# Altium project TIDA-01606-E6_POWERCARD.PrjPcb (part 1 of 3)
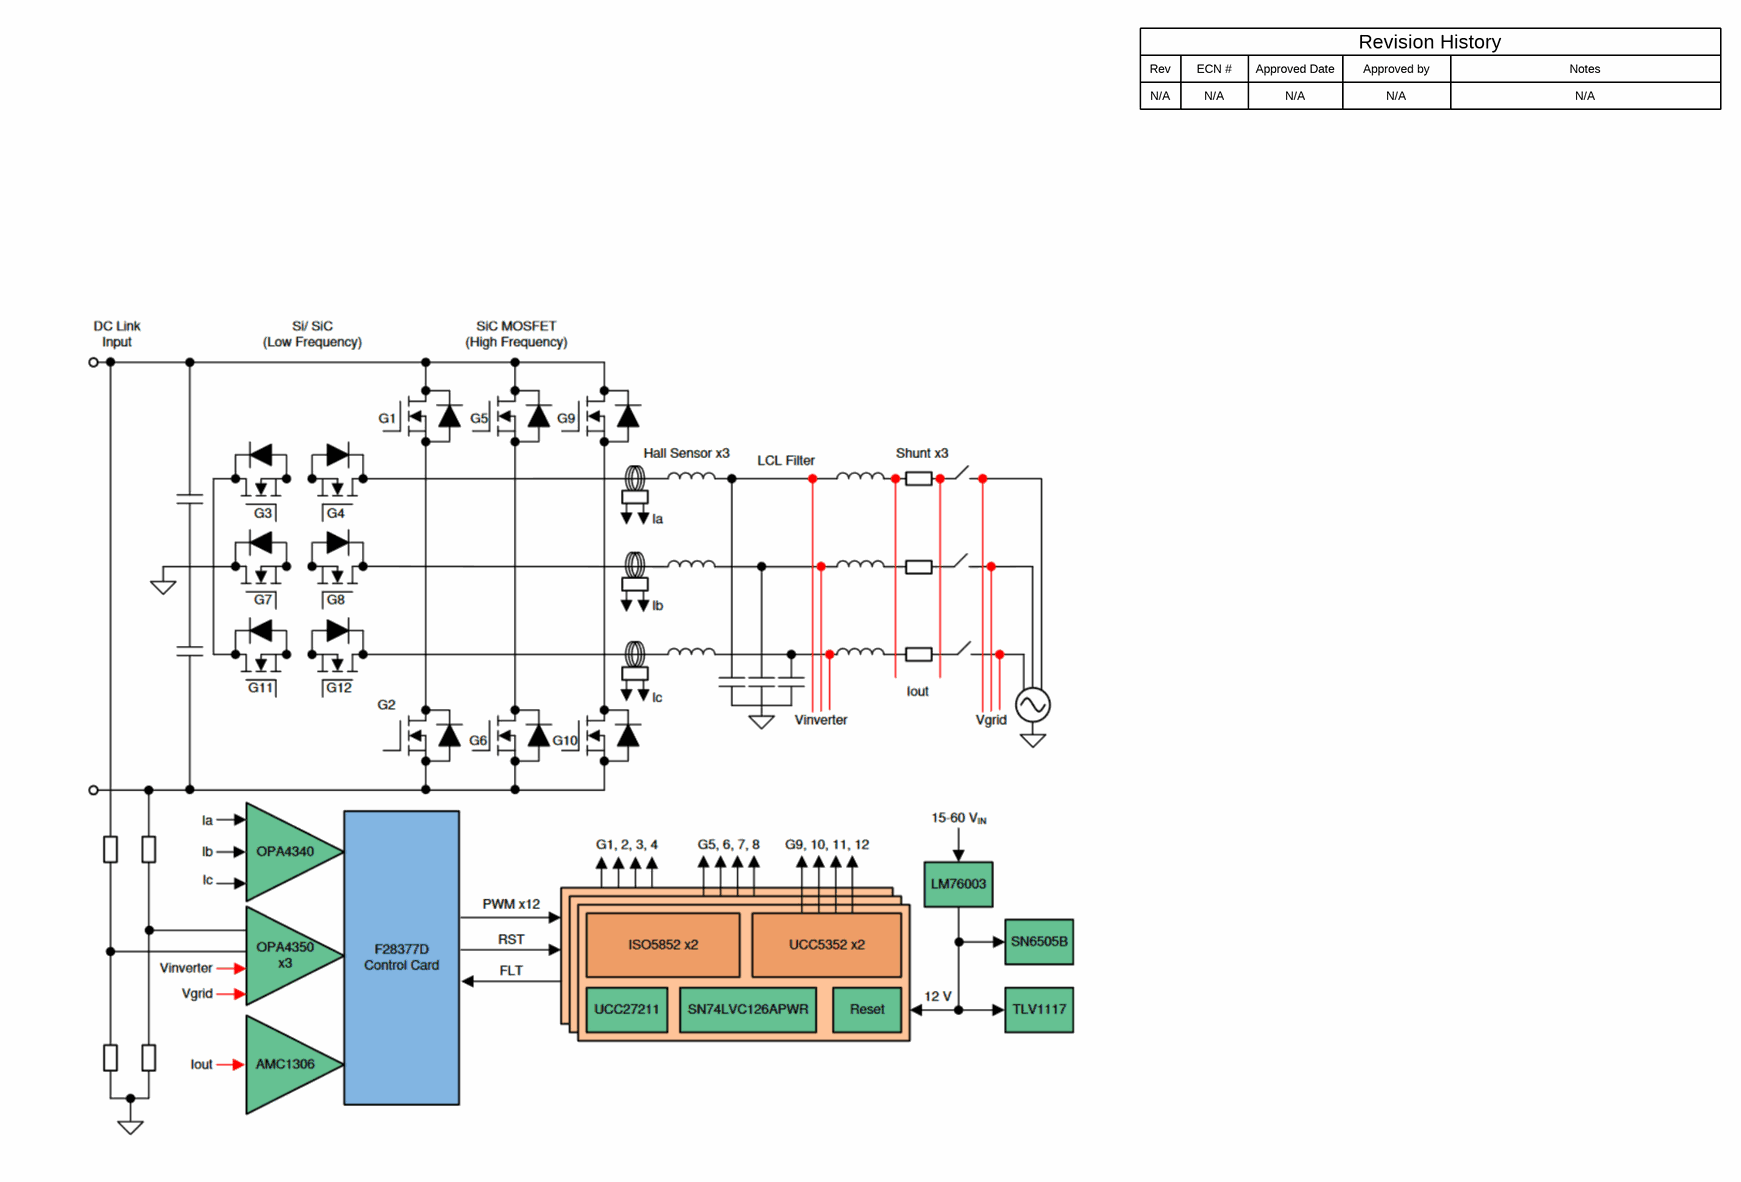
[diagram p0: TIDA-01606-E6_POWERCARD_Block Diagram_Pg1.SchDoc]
CopyrightYear: 2018; EVM_Orderable: NA; PCB_Layout: Bart Basile; PCB_Rev: E5; PRJ_Customer: Public Release; PRJ_Engineer: Bart Basile; PRJ_Number: TIDA-01606_Power Card; PRJ_Title: 10KW Inverter; SCH_Rev: E5; TechSupport: http://www.ti.com/support; TID: TIDA-01606
7 sheets, 551 parts. Net scope: global (net labels, ports and power ports of the same name join across sheets).
Board file: TIDA-01606-E6_POWERCARD.PcbDoc
Sheets:
  TIDA-01606-E6_POWERCARD_Block Diagram_Pg1.SchDoc
  TIDA-01606-E6_POWERCARD_Controller Card_Pg6.SchDoc
  TIDA-01606-E6_POWERCARD_Current Sensing_Pg5.SchDoc
  TIDA-01606-E6_POWERCARD_Hardware_Pg7.SchDoc
  TIDA-01606-E6_POWERCARD_Power Stage_Pg2.SchDoc
  TIDA-01606-E6_POWERCARD_Power Supply and Protection_Pg3.SchDoc
  TIDA-01606-E6_POWERCARD_Voltage Sensing_Pg4.SchDoc

## Sheet TIDA-01606-E6_POWERCARD_Block Diagram_Pg1.SchDoc
size 431 x 279 mm; Date: Not shown in title block; ApprovedBy: Not shown in title block; CheckedBy: Not shown in title block; Author: Not shown in title block; CompanyName: Not shown in title block; DrawnBy: Murali P; Engineer: Not shown in title block; Organization: Not shown in title block; Address1: Not shown in title block; Address2: Not shown in title block; Address3: Not shown in title block; Address4: Not shown in title block; DocumentNumber: 1; Revision: Use project parameter SCH_Rev; SheetNumber: 1; SheetTotal: 7; PageSetup: Record=PageOptions¦CenterHorizontal=True¦CenterVertical=True¦PrintScale=1.00¦XCorrection=1.00¦YCorrection=1.00¦PrintKind=0¦BorderSize=5000000¦LeftOffset=0¦BottomOffset=0¦Orientation=2¦PaperLength=1000¦PaperWidth=1000¦Scale=100¦PaperSource=15¦PrintQuality=600¦MediaType=1¦DitherType=10¦PaperKind=Letter¦PrintScaleMode=1

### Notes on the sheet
- Rev
- N/A
- ECN #
- Approved Date
- Approved by
- Revision History
- Notes

## Sheet TIDA-01606-E6_POWERCARD_Controller Card_Pg6.SchDoc
size 431 x 279 mm; Date: Not shown in title block; ApprovedBy: Not shown in title block; CheckedBy: Not shown in title block; Author: Not shown in title block; CompanyName: Not shown in title block; DrawnBy: Murali P; Engineer: Not shown in title block; Organization: Not shown in title block; Address1: Not shown in title block; Address2: Not shown in title block; Address3: Not shown in title block; Address4: Not shown in title block; DocumentNumber: 1; Revision: Use project parameter SCH_Rev; SheetNumber: 6; SheetTotal: 7; PageSetup: Record=PageOptions¦CenterHorizontal=True¦CenterVertical=True¦PrintScale=1.00¦XCorrection=1.00¦YCorrection=1.00¦PrintKind=0¦BorderSize=5000000¦LeftOffset=0¦BottomOffset=0¦Orientation=2¦PaperLength=1000¦PaperWidth=1000¦Scale=100¦PaperSource=15¦PrintQuality=600¦MediaType=1¦DitherType=10¦PrintScaleMode=1¦PaperKind=Letter
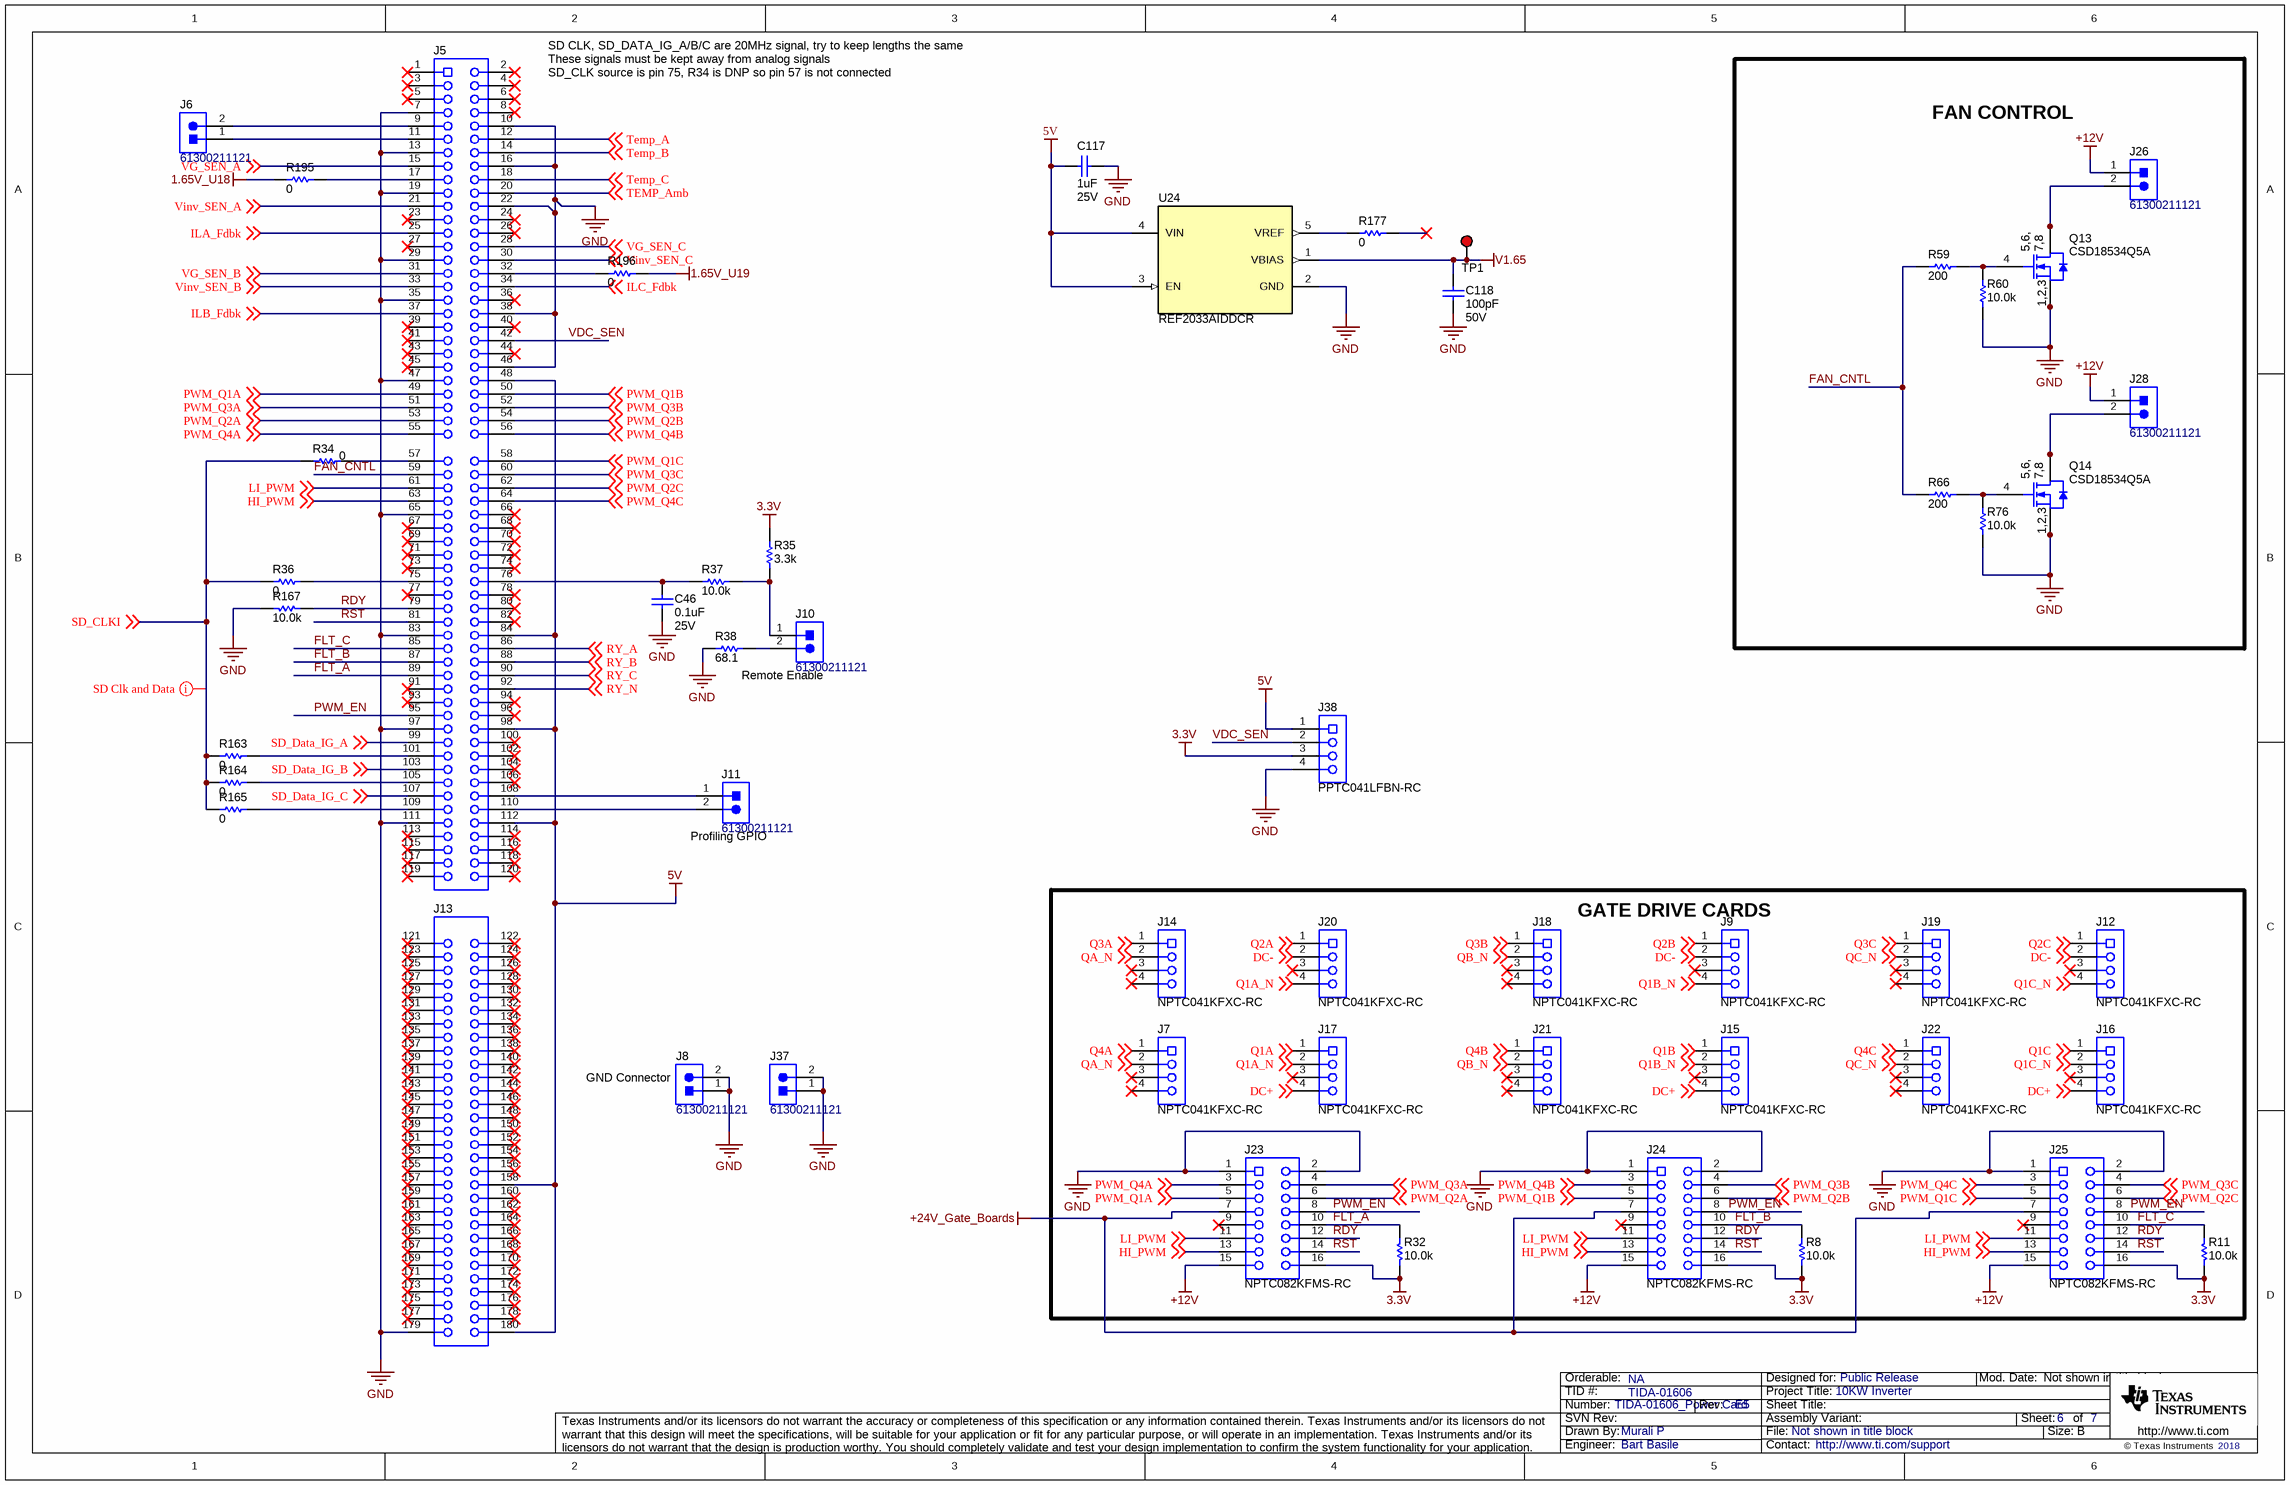
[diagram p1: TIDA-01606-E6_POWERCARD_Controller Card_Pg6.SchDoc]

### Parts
C46  ValueDisplayed: 0.1uF  VDC_V: 25V  [0603]  (hidden comment: C0603X104K3RACTU)
C117  ValueDisplayed: 1uF  VDC_V: 25V  [0603]  (hidden comment: C0603C105K3RACTU)
C118  ValueDisplayed: 100pF  VDC_V: 50V  [0603]  (hidden comment: CL10B101KB8NNNC)
J5  HSEC8-160-01-L-DV-A-BL  [controlCARD-120HSEC]  (value not drawn)
J6  61300211121  [WURTH_61300211121]
J7  NPTC041KFXC-RC  [Sullins_xPxC041KFXC-RC]
J8  61300211121  [WURTH_61300211121]
J9  NPTC041KFXC-RC  [Sullins_xPxC041KFXC-RC]
J10  61300211121  [WURTH_61300211121]
J11  61300211121  [WURTH_61300211121]
J12  NPTC041KFXC-RC  [Sullins_xPxC041KFXC-RC]
J13  HSEC8-130-01-L-DV-A  [controlCARD-180HSEC-60pinAddon]  (value not drawn)
J14  NPTC041KFXC-RC  [Sullins_xPxC041KFXC-RC]
J15  NPTC041KFXC-RC  [Sullins_xPxC041KFXC-RC]
J16  NPTC041KFXC-RC  [Sullins_xPxC041KFXC-RC]
J17  NPTC041KFXC-RC  [Sullins_xPxC041KFXC-RC]
J18  NPTC041KFXC-RC  [Sullins_xPxC041KFXC-RC]
J19  NPTC041KFXC-RC  [Sullins_xPxC041KFXC-RC]
J20  NPTC041KFXC-RC  [Sullins_xPxC041KFXC-RC]
J21  NPTC041KFXC-RC  [Sullins_xPxC041KFXC-RC]
J22  NPTC041KFXC-RC  [Sullins_xPxC041KFXC-RC]
J23  NPTC082KFMS-RC  [Sullins_xPxC082KFMS-RC]
J24  NPTC082KFMS-RC  [Sullins_xPxC082KFMS-RC]
J25  NPTC082KFMS-RC  [Sullins_xPxC082KFMS-RC]
J26  61300211121  [WURTH_61300211121]
J28  61300211121  [WURTH_61300211121]
J37  61300211121  [WURTH_61300211121]
J38  PPTC041LFBN-RC  [Sullins_xPxC041LFBN]
Q13  CSD18534Q5A  [DQJ0008A]
Q14  CSD18534Q5A  [DQJ0008A]
R8  ValueDisplayed: 10.0k  [0603]  (hidden comment: ERJ-3EKF1002V)
R11  ValueDisplayed: 10.0k  [0603]  (hidden comment: ERJ-3EKF1002V)
R32  ValueDisplayed: 10.0k  [0603]  (hidden comment: ERJ-3EKF1002V)
R34  ValueDisplayed: 0  [0603]  (hidden comment: RCS06030000Z0EA)
R35  ValueDisplayed: 3.3k  [0805_HV]  (hidden comment: CRCW08053K30JNEA)
R36  ValueDisplayed: 0  [0603]  (hidden comment: RCS06030000Z0EA)
R37  ValueDisplayed: 10.0k  [0603]  (hidden comment: ERJ-3EKF1002V)
R38  ValueDisplayed: 68.1  [0603]  (hidden comment: CRCW060368R1FKEA)
R59  ValueDisplayed: 200  [0805_HV]  (hidden comment: CRCW0805200RFKEA)
R60  ValueDisplayed: 10.0k  [0603]  (hidden comment: ERJ-3EKF1002V)
R66  ValueDisplayed: 200  [0805_HV]  (hidden comment: CRCW0805200RFKEA)
R76  ValueDisplayed: 10.0k  [0603]  (hidden comment: ERJ-3EKF1002V)
R163  ValueDisplayed: 0  [0603]  (hidden comment: RCS06030000Z0EA)
R164  ValueDisplayed: 0  [0603]  (hidden comment: RCS06030000Z0EA)
R165  ValueDisplayed: 0  [0603]  (hidden comment: RCS06030000Z0EA)
R167  ValueDisplayed: 10.0k  [0603]  (hidden comment: ERJ-3EKF1002V)
R177  ValueDisplayed: 0  [0805_HV]  (hidden comment: ERJ-6GEY0R00V)
R195  ValueDisplayed: 0  [0805_HV]  (hidden comment: ERJ-6GEY0R00V)
R196  ValueDisplayed: 0  [0805_HV]  (hidden comment: ERJ-6GEY0R00V)
TP1  5000  [Keystone5000]  (value not drawn)
U24  REF2033AIDDCR  [DDC0005A_N]

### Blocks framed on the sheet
FAN CONTROL: J26 J28 Q13 Q14 R59 R60 R66 R76
GATE DRIVE CARDS: J7 J9 J12 J14-J25 R8 R11 R32

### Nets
1.65V_U18: R195.2
1.65V_U19: R196.2
3.3V: J23.16 J24.16 J25.16 J38.3 R8.2 R11.2 R32.2 R35.2
5V: C117.2 J5.48 J5.84 J5.98 J5.112 J13.158 J13.180 J38.1 U24.3(EN) U24.4(VIN)
+12V: J23.15 J24.15 J25.15 J26.1 J28.1
+24V_Gate_Boards: J23.7 J24.7 J25.7
GND: C46.1 C117.1 C118.2 J5.7 J5.10 J5.13 J5.16 J5.19 J5.22 J5.29 J5.35 J5.38 J5.46 J5.47 J5.65 J5.83 J5.97 J5.111 J8.1 J8.2 J13.179 J23.1 J23.2 J24.1 J24.2 J25.1 J25.2 J37.1 J37.2 J38.4 Q13.1(S) Q13.2(S) Q13.3(S) Q14.1(S) Q14.2(S) Q14.3(S) R38.1 R60.1 R76.1 R167.1 U24.2(GND)
V1.65: C118.1 TP1.1 U24.1(VBIAS)
DC+: J15.4 J16.4 J17.4 ; off-sheet DC+
DC-: J9.2 J12.2 J20.2 ; off-sheet DC-
FAN_CNTL: J5.59 R59.1 R66.1
FLT_A: J5.89 J23.10 R32.1
FLT_B: J5.87 J24.10 R8.1
FLT_C: J5.85 J25.10 R11.1
HI_PWM: J5.63 J23.13 J24.13 J25.13 ; off-sheet HI_PWM
ILA_Fdbk: J5.25 ; off-sheet ILA_Fdbk
ILB_Fdbk: J5.37 ; off-sheet ILB_Fdbk
ILC_Fdbk: J5.34 ; off-sheet ILC_Fdbk
LI_PWM: J5.61 J23.11 J24.11 J25.11 ; off-sheet LI_PWM
PWM_EN: J5.95 J23.8 J24.8 J25.8
PWM_Q1A: J5.49 J23.5 ; off-sheet PWM_Q1A
PWM_Q1B: J5.50 J24.5 ; off-sheet PWM_Q1B
PWM_Q1C: J5.58 J25.5 ; off-sheet PWM_Q1C
PWM_Q2A: J5.53 J23.6 ; off-sheet PWM_Q2A
PWM_Q2B: J5.54 J24.6 ; off-sheet PWM_Q2B
PWM_Q2C: J5.62 J25.6 ; off-sheet PWM_Q2C
PWM_Q3A: J5.51 J23.4 ; off-sheet PWM_Q3A
PWM_Q3B: J5.52 J24.4 ; off-sheet PWM_Q3B
PWM_Q3C: J5.60 J25.4 ; off-sheet PWM_Q3C
PWM_Q4A: J5.55 J23.3 ; off-sheet PWM_Q4A
PWM_Q4B: J5.56 J24.3 ; off-sheet PWM_Q4B
PWM_Q4C: J5.64 J25.3 ; off-sheet PWM_Q4C
Q1A: J17.1 ; off-sheet Q1A
Q1A_N: J17.2 J20.4 ; off-sheet Q1A_N  [project net Iind_A]
Q1B: J15.1 ; off-sheet Q1B
Q1B_N: J9.4 J15.2 ; off-sheet Q1B_N  [project net Iind_B]
Q1C: J16.1 ; off-sheet Q1C
Q1C_N: J12.4 J16.2 ; off-sheet Q1C_N  [project net Iind_C]
Q2A: J20.1 ; off-sheet Q2A
Q2B: J9.1 ; off-sheet Q2B
Q2C: J12.1 ; off-sheet Q2C
Q3A: J14.1 ; off-sheet Q3A
Q3B: J18.1 ; off-sheet Q3B
Q3C: J19.1 ; off-sheet Q3C
Q4A: J7.1 ; off-sheet Q4A
Q4B: J21.1 ; off-sheet Q4B
Q4C: J22.1 ; off-sheet Q4C
QA_N: J7.2 J14.2 ; off-sheet QA_N
QB_N: J18.2 J21.2 ; off-sheet QB_N
QC_N: J19.2 J22.2 ; off-sheet QC_N
RDY: J5.79 J23.12 J24.12 J25.12 R167.2
RST: J5.81 J23.14 J24.14 J25.14
RY_A: J5.86 ; off-sheet RY_A
RY_B: J5.88 ; off-sheet RY_B
RY_C: J5.90 ; off-sheet RY_C
RY_N: J5.92 ; off-sheet RY_N
SD_CLKI: R34.1 R36.1 R163.1 R164.1 R165.1 ; off-sheet SD_CLKI
SD_Data_IG_A: J5.99 ; off-sheet SD_Data_IG_A
SD_Data_IG_B: J5.103 ; off-sheet SD_Data_IG_B
SD_Data_IG_C: J5.107 ; off-sheet SD_Data_IG_C
Temp_A: J5.12 ; off-sheet Temp_A
TEMP_Amb: J5.20 ; off-sheet TEMP_Amb
Temp_B: J5.14 ; off-sheet Temp_B
Temp_C: J5.18 ; off-sheet Temp_C
VDC_SEN: J5.42 J38.2
VG_SEN_A: J5.15 ; off-sheet VG_SEN_A
VG_SEN_B: J5.31 ; off-sheet VG_SEN_B
VG_SEN_C: J5.28 ; off-sheet VG_SEN_C
Vinv_SEN_A: J5.21 ; off-sheet Vinv_SEN_A
Vinv_SEN_B: J5.33 ; off-sheet Vinv_SEN_B
Vinv_SEN_C: J5.30 ; off-sheet Vinv_SEN_C
NetC46_2: C46.2 J5.76 R37.2
NetJ5_9: J5.9 J6.2
NetJ5_11: J5.11 J6.1
NetJ5_17: J5.17 R195.1
NetJ5_32: J5.32 R196.1
NetJ5_57: J5.57 R34.2
NetJ5_75: J5.75 R36.2
NetJ5_101: J5.101 R163.2
NetJ5_105: J5.105 R164.2
NetJ5_108: J5.108 J11.1
NetJ5_109: J5.109 R165.2
NetJ5_110: J5.110 J11.2
NetJ10_1: J10.1 R35.1 R37.1
NetJ10_2: J10.2 R38.2
NetJ26_2: J26.2 Q13.5(D) Q13.6(D) Q13.7(D) Q13.8(D) Q13.9(D)
NetJ28_2: J28.2 Q14.5(D) Q14.6(D) Q14.7(D) Q14.8(D) Q14.9(D)
NetQ13_4: Q13.4(G) R59.2 R60.2
NetQ14_4: Q14.4(G) R66.2 R76.2
NetR177_2: R177.2 U24.5(VREF)

Not connected (* = marked no-connect by the designer): J5 1* 2* 3* 4* 5* 6* 8* 23* 24* 26* 27* 36* 39* 40* 41* 43* 44* 45* 66* 67* 68* 69* 70* 71* 72* 73* 74* 77* 78* 80* 82* 91* 93* 94* 96* 100* 102* 104* 106* 113* 114* 115* 116* 117* 118* 119* 120*; J7 3* 4*; J9 3*; J12 3*; J13 121* 122* 123* 124* 125* 126* 127* 128* 129* 130* 131* 132* 133* 134* 135* 136* 137* 138* 139* 140* 141* 142* 143* 144* 145* 146* 147* 148* 149* 150* 151* 152* 153* 154* 155* 156* 157* 159* 160* 161* 162* 163* 164* 165* 166* 167* 168* 169* 170* 171* 172* 173* 174* 175* 176* 177* 178*; J14 3* 4*; J15 3*; J16 3*; J17 3*; J18 3* 4*; J19 3* 4*; J20 3*; J21 3* 4*; J22 3* 4*; J23 9*; J24 9*; J25 9*; R177 1*

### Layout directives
rule Undefined: SD_CLKI

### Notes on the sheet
- (near J5) These signals must be kept away from analog signals
- (near J5) SD_CLK source is pin 75, R34 is DNP so pin 57 is not connected
- SD CLK, SD_DATA_IG_A/B/C are 20MHz signal, try to keep lengths the same
- Remote Enable
- (near J11) Profiling GPIO
- (near J8) GND Connector

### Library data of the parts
C46 = CMP-0006979-5: CAP, CERM, 0.1 uF, 25 V, +/- 10%, X7R, 0603; Manufacturer: Kemet; Polarized: N; Value: 0.1uF; U/M: EA; Cap_F: 100nF; Value1: Unknown; TaMin_C: -55°C; TaMax_C: 125°C; AEC Category: Q200; SizeArea_mm2: 1.28; SizeAreaWB_mm2: 4.68; SizeX_mm: 1.6; SizeY_mm: 0.8; SizeZ_mm: 1
C117 = CMP-0006867-4: CAP, CERM, 1 uF, 25 V, +/- 10%, X7R, 0603; Manufacturer: Kemet; Polarized: N; Value: 1uF; U/M: EA; Cap_F: 1µF; Value1: Unknown; TaMin_C: -55°C; TaMax_C: 125°C; AEC Category: Q200; SizeArea_mm2: 1.28; SizeAreaWB_mm2: 4.68; SizeX_mm: 1.6; SizeY_mm: 0.8; SizeZ_mm: 1
C118 = CMP-0083857-1: CAP, CERM, 100 pF, 50 V,+/- 10%, X7R, 0603; Manufacturer: Samsung Electro-Mechanics; Polarized: N; Value: 100pF; U/M: EA; TaMin_C: -55°C; TaMax_C: 125°C; SizeArea_mm2: 1.28; SizeAreaWB_mm2: 4.68; SizeX_mm: 1.6; SizeY_mm: 0.8; SizeZ_mm: 1; AEC Category: Q200
J5 = CMP-0003814-2: C2000 controlCARD-120HSEC connector, SMT; Manufacturer: Samtec; Note: The pin numbering does not match Samtec datasheet
J6 J8 J10 J11 J26 J28 J37 = CMP-0054794-2: Header, 2.54 mm, 2x1, Gold, TH; Manufacturer: Wurth Elektronik; Green_Lifecycle: Active; Green_REACh: Passed; Cert_UL: Y; Gender: Male; Pitch_mm: 2.54; Row_Count: 1; Shrouded: N
J7 J9 J12 J14-J22 = CMP-0083775-2: Receptacle, 2.54mm, 4x1, Tin, SMT; Manufacturer: Sullins Connector Solutions; Pitch_mm: 2.54; Gender: Female; Voltage_V: 250V; CompType: Socket Strip; Row_Count: 1; Current_A: 3A; Cert_UL: Y
J13 = CMP-0003859-2: C2000 controlCARD-180HSEC (60-pin addon) connector, SMT; Manufacturer: Samtec; Note: The pin numbering does not match Samtec datasheet
J23-J25 = CMP-0083774-2: Receptacle, 2.54mm, 8x2, Tin, SMT; Manufacturer: Sullins Connector Solutions; Current_A: 3A; Gender: Female; Voltage_V: 250V; CompType: Socket Strip; Row_Count: 2; RowSpacing_mm: 2.54; Cert_UL: Y
J38 = CMP-0054676-1: Receptacle, 2.54mm, 4x1, Tin, TH; Manufacturer: Sullins Connector Solutions; CompType: Socket Strip; Pitch_mm: 2.54; Gender: Female; Row_Count: 1; Current_A: 3A; Voltage_V: 250V; Cert_UL: Y; CNHeader: FALSE; CT: TRUE
Q13 Q14 = CMP-0000817-1: MOSFET, N-CH, 60 V, 50 A, DQJ0008A (VSONP-8); Manufacturer: Texas Instruments; Alternate Manufacturer: None; U/M: EA; ChType: N; Value: 60V; Value1: 0.009; Rdson45_ohm: 9.8m; Value2: 22 nC; QgTyp_nC: 22; Vgs_V: 2.3V; IdsMax_A: 50A; SizeAreaWB_mm2: 55.2; SizeArea_mm2: 29.4; SizeX_mm: 6; SizeY_mm: 4.9; SizeZ_mm: 1.1; AEC Category: Q101
R8 R11 R32 R60 R76 R167 = CMP-0022684-3: RES, 10.0 k, 1%, 0.1 W, 0603; Manufacturer: Panasonic; Value: 10.0k; Res_ohm: 10k; Value_Code: 10k0; Power_W: 100mW; Value2: 0.1W; VDC_V: 75V; TempCo: 100 ppm/C; SizeArea_mm2: 1.28; SizeX_mm: 1.6; SizeY_mm: 0.8; SizeZ_mm: 1; EIA_Code: E96; U/M: EA; AEC Category: Q200
R34 R36 R163-R165 = CMP-0081973-1: RES, 0, 0%, 0.25 W, AEC-Q200 Grade 0, 0603; Manufacturer: Vishay-Dale; SizeAreaWB_mm2: 4.68; SizeArea_mm2: 1.28; AEC Qualified: Y; AEC Category: Q200; Value: 0; SizeZ_mm: 1; SizeY_mm: 0.8; Power_W: 250mW; Value2: 0.25W; SizeX_mm: 1.6
R35 = CMP-0020539-3: RES, 3.3 k, 5%, 0.125 W, AEC-Q200 Grade 0, 0805; Manufacturer: Vishay-Dale; Value: 3.3k; Value_Code: 3k30; Power_W: 125mW; Value2: 0.125W; VDC_V: 150V; TempCo: 200 ppm/C; EIA_Code: E24; AEC Category: Q200; AEC Qualified: Y; AEC Grade: 0; SizeArea_mm2: 2.5; SizeX_mm: 2; SizeY_mm: 1.25; SizeZ_mm: 1.45
R37 = CMP-0022684-3: RES, 10.0 k, 1%, 0.1 W, 0603; Manufacturer: Panasonic; Value: 10.0k; Res_ohm: 10k; Value_Code: 10k0; Power_W: 100mW; Value2: 0.1W; VDC_V: 75V; TempCo: 100 ppm/C; EIA_Code: E96; U/M: EA; AEC Category: Q200; SizeArea_mm2: 1.28; SizeX_mm: 1.6; SizeY_mm: 0.8; SizeZ_mm: 1
R38 = CMP-0022553-4: RES, 68.1, 1%, 0.1 W, AEC-Q200 Grade 0, 0603; Manufacturer: Vishay-Dale; Value: 68.1; Value_Code: 68R1; Power_W: 100mW; Value2: 0.1W; VDC_V: 75V; TempCo: 100 ppm/C; SizeArea_mm2: 1.28; SizeX_mm: 1.6; SizeY_mm: 0.8; SizeZ_mm: 1; EIA_Code: E96; AEC Category: Q200; AEC Qualified: Y; AEC Grade: 0
R59 R66 = CMP-0021039-3: RES, 200, 1%, 0.125 W, AEC-Q200 Grade 0, 0805; Manufacturer: Vishay-Dale; Value: 200; Value_Code: 200R; Power_W: 125mW; Value2: 0.125W; VDC_V: 150V; TempCo: 100 ppm/C; SizeArea_mm2: 2.5; SizeX_mm: 2; SizeY_mm: 1.25; SizeZ_mm: 1.45; EIA_Code: E96; AEC Category: Q200; AEC Qualified: Y; AEC Grade: 0
R177 R195 R196 = CMP-0020616-3: RES, 0, 5%, 0.125 W, AEC-Q200 Grade 0, 0805; Manufacturer: Panasonic; Value: 0; Value_Code: 0000; Power_W: 125mW; Value2: 0.125W; VDC_V: 150V; TempCo: 600 ppm/C; EIA_Code: E24; AEC Category: Q200; AEC Qualified: Y; SizeArea_mm2: 2.5; SizeX_mm: 2; SizeY_mm: 1.25; SizeZ_mm: 1.45; SizeAreaWB_mm2: 6.75
TP1 = CMP-0055137-1: Test Point, Miniature, Red, TH; Manufacturer: Keystone; CNHeader: FALSE; ContactFinish: Silver; CT: TRUE; Green_Lifecycle: Active; Green_REACh: Passed
U24 = CMP-0066190-1: Low-Drift, Low-Power, Dual-Output VREF and VREF/2 Voltage Reference, DDC0005A (SOT-23-T-5); Alternate PartNumber: REF2033AIDDCT; Manufacturer: Texas Instruments; CompType: IC; U/M: EA; SizeArea_mm2: 8.12; SizeAreaWB_mm2: 14.82; SizeX_mm: 2.8; SizeY_mm: 2.9; SizeZ_mm: 1.1

## Sheet TIDA-01606-E6_POWERCARD_Current Sensing_Pg5.SchDoc: Inductor Current Sensing Interface Circuit
size 431 x 279 mm; Date: Not shown in title block; ApprovedBy: Not shown in title block; CheckedBy: Not shown in title block; Author: Not shown in title block; CompanyName: Not shown in title block; DrawnBy: Murali P; Engineer: Not shown in title block; Organization: Not shown in title block; Address1: Not shown in title block; Address2: Not shown in title block; Address3: Not shown in title block; Address4: Not shown in title block; DocumentNumber: 1; Revision: Use project parameter SCH_Rev; SheetNumber: 3; SheetTotal: 7; PageSetup: Record=PageOptions¦CenterHorizontal=True¦CenterVertical=True¦PrintScale=1.00¦XCorrection=1.00¦YCorrection=1.00¦PrintKind=0¦BorderSize=5000000¦LeftOffset=0¦BottomOffset=0¦Orientation=2¦PaperLength=1000¦PaperWidth=1000¦Scale=100¦PaperSource=15¦PrintQuality=600¦MediaType=1¦DitherType=10¦PaperKind=Letter¦PrintScaleMode=1
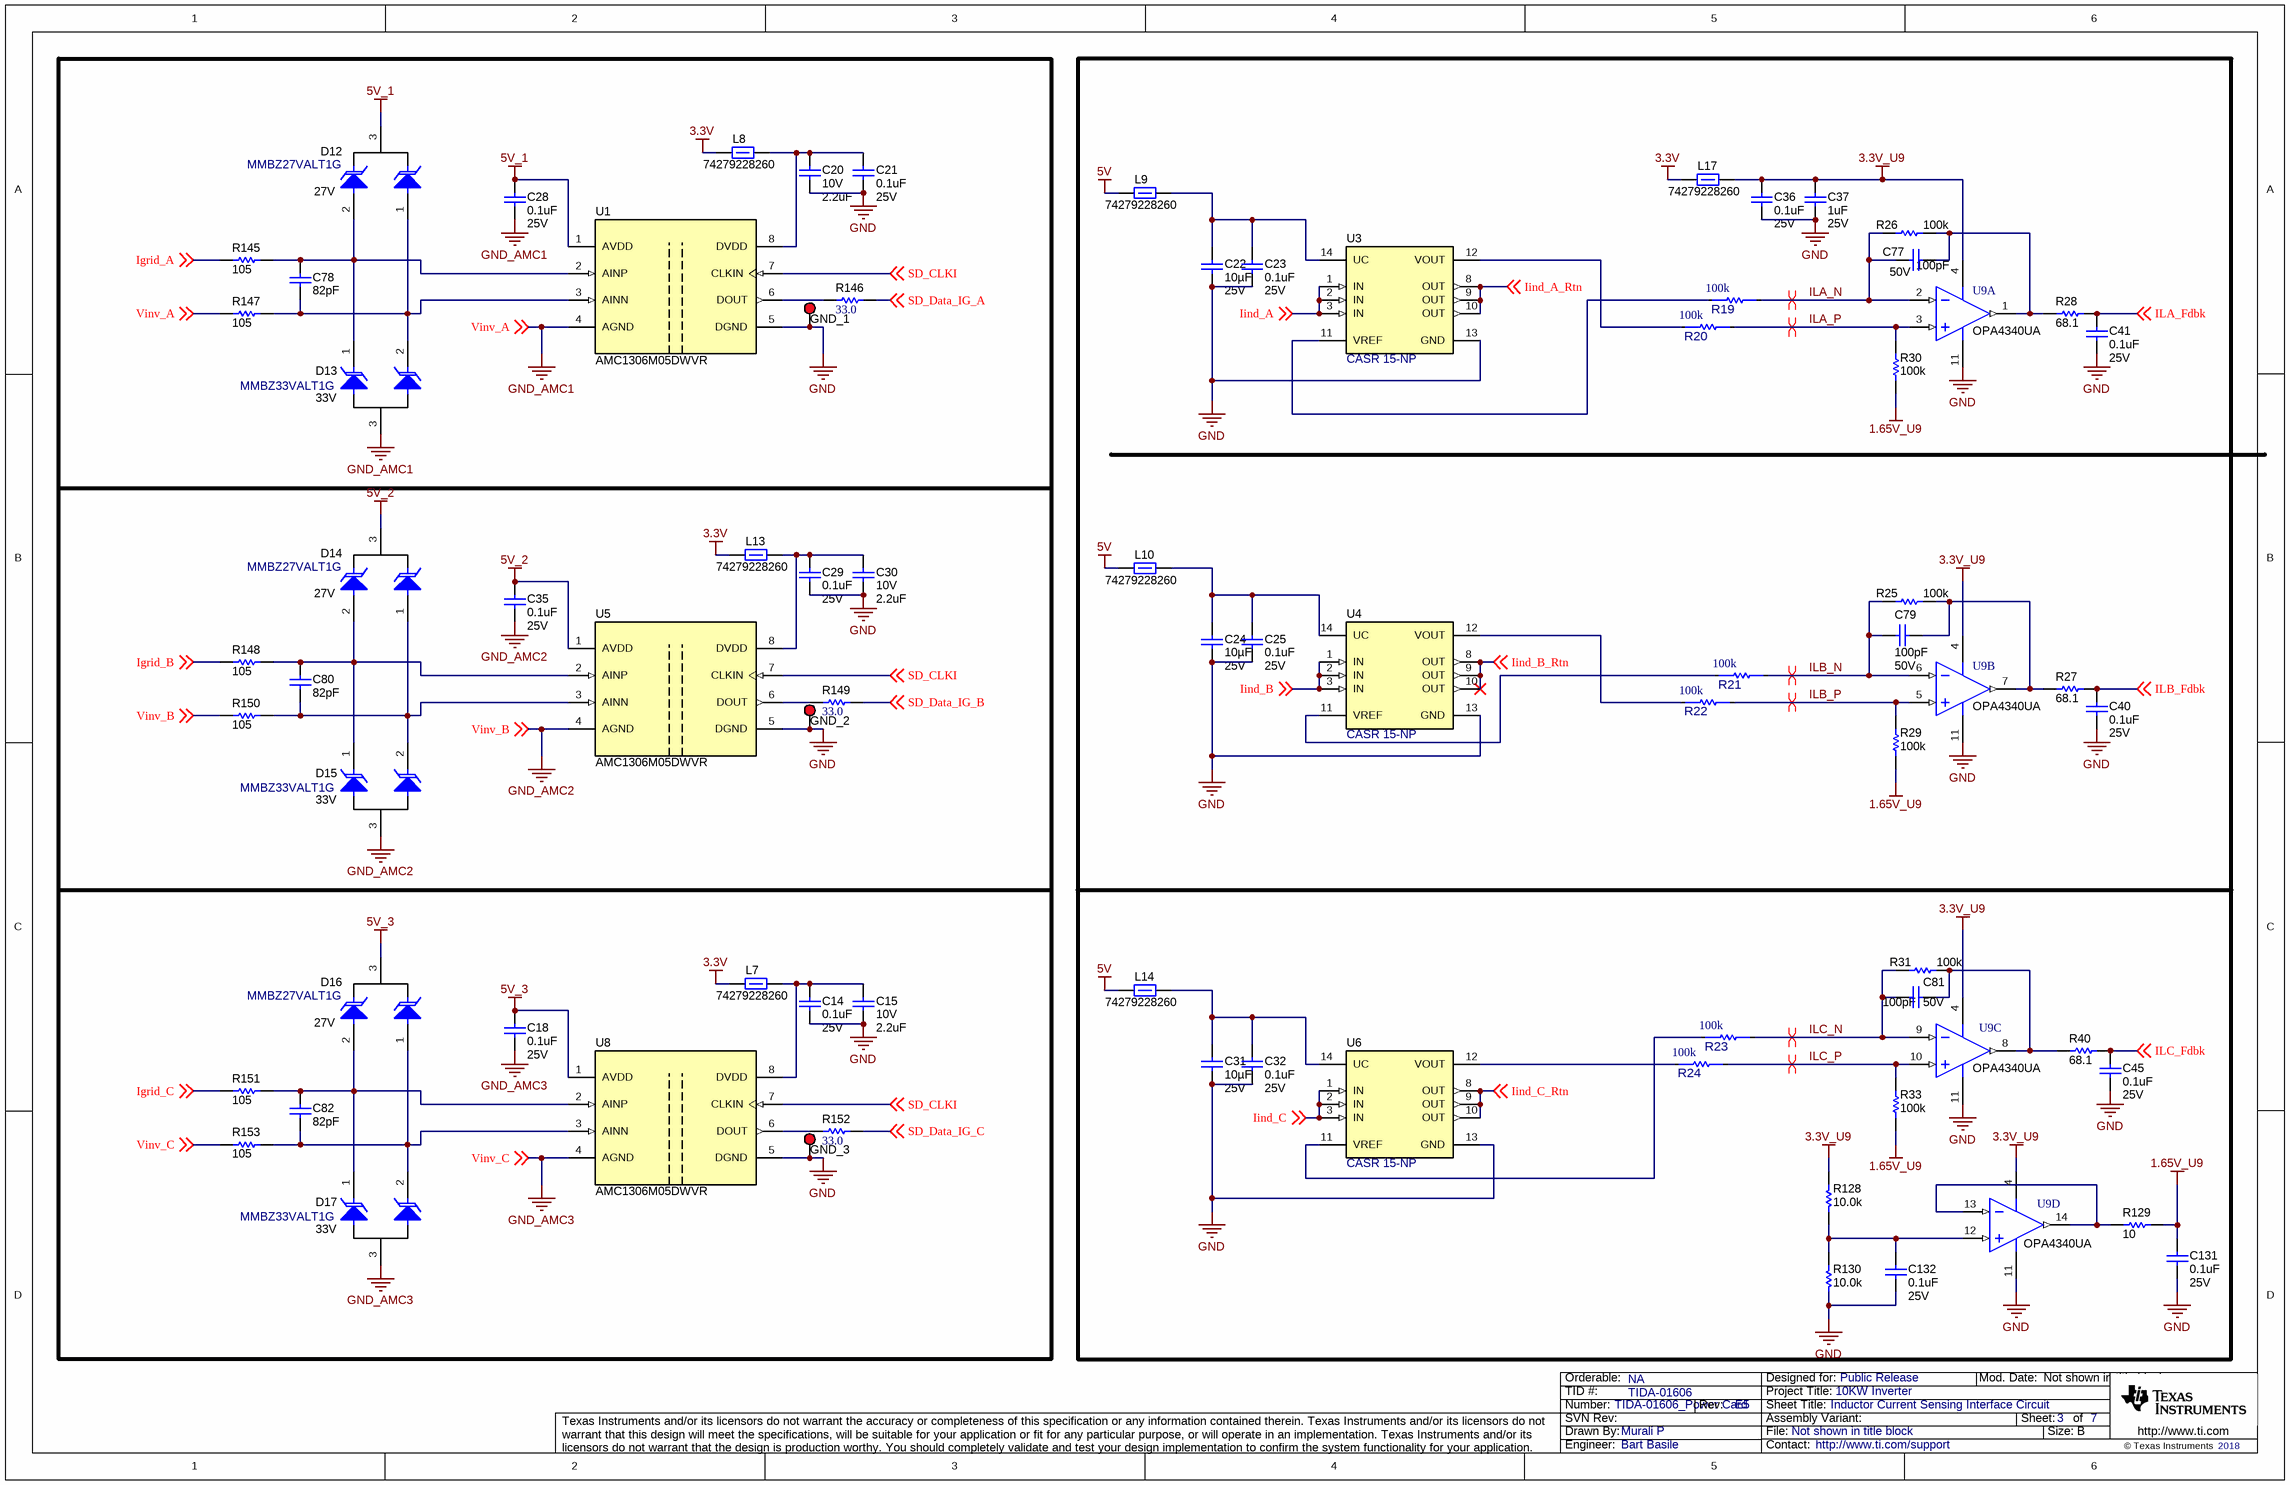
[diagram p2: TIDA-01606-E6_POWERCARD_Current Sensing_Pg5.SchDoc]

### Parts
C14  ValueDisplayed: 0.1uF  VDC_V: 25V  [0603]  (hidden comment: C0603X104K3RACTU)
C15  VDC_V: 10V  ValueDisplayed: 2.2uF  [0805_HV]  (hidden comment: GRM216R61A225KE24D)
C18  ValueDisplayed: 0.1uF  VDC_V: 25V  [0603]  (hidden comment: C0603X104K3RACTU)
C20  VDC_V: 10V  ValueDisplayed: 2.2uF  [0805_HV]  (hidden comment: GRM216R61A225KE24D)
C21  ValueDisplayed: 0.1uF  VDC_V: 25V  [0603]  (hidden comment: C0603X104K3RACTU)
C22  ValueDisplayed: 10µF  VDC_V: 25V  [1206_180]  (hidden comment: C3216X7R1E106K160AB)
C23  ValueDisplayed: 0.1uF  VDC_V: 25V  [0603]  (hidden comment: C0603X104K3RACTU)
C24  ValueDisplayed: 10µF  VDC_V: 25V  [1206_180]  (hidden comment: C3216X7R1E106K160AB)
C25  ValueDisplayed: 0.1uF  VDC_V: 25V  [0603]  (hidden comment: C0603X104K3RACTU)
C28  ValueDisplayed: 0.1uF  VDC_V: 25V  [0603]  (hidden comment: C0603X104K3RACTU)
C29  ValueDisplayed: 0.1uF  VDC_V: 25V  [0603]  (hidden comment: C0603X104K3RACTU)
C30  VDC_V: 10V  ValueDisplayed: 2.2uF  [0805_HV]  (hidden comment: GRM216R61A225KE24D)
C31  ValueDisplayed: 10µF  VDC_V: 25V  [1206_180]  (hidden comment: C3216X7R1E106K160AB)
C32  ValueDisplayed: 0.1uF  VDC_V: 25V  [0603]  (hidden comment: C0603X104K3RACTU)
C35  ValueDisplayed: 0.1uF  VDC_V: 25V  [0603]  (hidden comment: C0603X104K3RACTU)
C36  ValueDisplayed: 0.1uF  VDC_V: 25V  [0603]  (hidden comment: C0603X104K3RACTU)
C37  ValueDisplayed: 1uF  VDC_V: 25V  [0603]  (hidden comment: C0603C105K3RACTU)
C40  ValueDisplayed: 0.1uF  VDC_V: 25V  [0603]  (hidden comment: C0603X104K3RACTU)
C41  ValueDisplayed: 0.1uF  VDC_V: 25V  [0603]  (hidden comment: C0603X104K3RACTU)
C45  ValueDisplayed: 0.1uF  VDC_V: 25V  [0603]  (hidden comment: C0603X104K3RACTU)
C77  ValueDisplayed: 100pF  VDC_V: 50V  [0603]  (hidden comment: CL10B101KB8NNNC)
C78  ValueDisplayed: 82pF  [0603]  (hidden comment: 06035A820JAT2A)
C79  ValueDisplayed: 100pF  VDC_V: 50V  [0603]  (hidden comment: CL10B101KB8NNNC)
C80  ValueDisplayed: 82pF  [0603]  (hidden comment: 06035A820JAT2A)
C81  ValueDisplayed: 100pF  VDC_V: 50V  [0603]  (hidden comment: CL10B101KB8NNNC)
C82  ValueDisplayed: 82pF  [0603]  (hidden comment: 06035A820JAT2A)
C131  ValueDisplayed: 0.1uF  VDC_V: 25V  [0603]  (hidden comment: C0603X104K3RACTU)
C132  ValueDisplayed: 0.1uF  VDC_V: 25V  [0603]  (hidden comment: C0603X104K3RACTU)
D12  MMBZ27VALT1G  value 27V  [SOT-23]
D13  MMBZ33VALT1G  value 33V  [SOT-23]
D14  MMBZ27VALT1G  value 27V  [SOT-23]
D15  MMBZ33VALT1G  value 33V  [SOT-23]
D16  MMBZ27VALT1G  value 27V  [SOT-23]
D17  MMBZ33VALT1G  value 33V  [SOT-23]
GND_1  5000  [Keystone5000]  (value not drawn)
GND_2  5000  [Keystone5000]  (value not drawn)
GND_3  5000  [Keystone5000]  (value not drawn)
L7  74279228260  [0603]
L8  74279228260  [0603]
L9  74279228260  [0603]
L10  74279228260  [0603]
L13  74279228260  [0603]
L14  74279228260  [0603]
L17  74279228260  [0603]
R19  value 100k  [FP-ERJ-PB3B1003V_0603-MFG]  (hidden comment: ERJ-PB3B1003V)
R20  value 100k  [FP-ERJ-PB3B1003V_0603-MFG]  (hidden comment: ERJ-PB3B1003V)
R21  value 100k  [FP-ERJ-PB3B1003V_0603-MFG]  (hidden comment: ERJ-PB3B1003V)
R22  value 100k  [FP-ERJ-PB3B1003V_0603-MFG]  (hidden comment: ERJ-PB3B1003V)
R23  value 100k  [FP-ERJ-PB3B1003V_0603-MFG]  (hidden comment: ERJ-PB3B1003V)
R24  value 100k  [FP-ERJ-PB3B1003V_0603-MFG]  (hidden comment: ERJ-PB3B1003V)
R25  ValueDisplayed: 100k  [0603]  (hidden comment: CRCW0603100KFKEA)
R26  ValueDisplayed: 100k  [0603]  (hidden comment: CRCW0603100KFKEA)
R27  ValueDisplayed: 68.1  [0603]  (hidden comment: CRCW060368R1FKEA)
R28  ValueDisplayed: 68.1  [0603]  (hidden comment: CRCW060368R1FKEA)
R29  ValueDisplayed: 100k  [0603]  (hidden comment: CRCW0603100KFKEA)
R30  ValueDisplayed: 100k  [0603]  (hidden comment: CRCW0603100KFKEA)
R31  ValueDisplayed: 100k  [0603]  (hidden comment: CRCW0603100KFKEA)
R33  ValueDisplayed: 100k  [0603]  (hidden comment: CRCW0603100KFKEA)
R40  ValueDisplayed: 68.1  [0603]  (hidden comment: CRCW060368R1FKEA)
R128  ValueDisplayed: 10.0k  [0603]  (hidden comment: RG1608P-103-B-T5)
R129  ValueDisplayed: 10  [0603]  (hidden comment: CRCW060310R0JNEA)
R130  ValueDisplayed: 10.0k  [0603]  (hidden comment: RG1608P-103-B-T5)
R145  ValueDisplayed: 105  [0603]  (hidden comment: CRCW0603105RFKEA)
R146  ValueDisplayed: 33.0  [0603]  (hidden comment: RC0603FR-0733RL)
R147  ValueDisplayed: 105  [0603]  (hidden comment: CRCW0603105RFKEA)
R148  ValueDisplayed: 105  [0603]  (hidden comment: CRCW0603105RFKEA)
R149  ValueDisplayed: 33.0  [0603]  (hidden comment: RC0603FR-0733RL)
R150  ValueDisplayed: 105  [0603]  (hidden comment: CRCW0603105RFKEA)
R151  ValueDisplayed: 105  [0603]  (hidden comment: CRCW0603105RFKEA)
R152  ValueDisplayed: 33.0  [0603]  (hidden comment: RC0603FR-0733RL)
R153  ValueDisplayed: 105  [0603]  (hidden comment: CRCW0603105RFKEA)
U1  AMC1306M05DWVR  [DWV0008A]
U3  CASR 15-NP  [CASR]
U4  CASR 15-NP  [CASR]
U5  AMC1306M05DWVR  [DWV0008A]
U6  CASR 15-NP  [CASR]
U8  AMC1306M05DWVR  [DWV0008A]
U9  OPA4340UA  [D0014A_N]  (parts A,B,C,D of 4)

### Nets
1.65V_U9: C131.2 R29.1 R30.1 R33.1 R129.2
3.3V: L7.1 L8.1 L13.1 L17.1
3.3V_U9: C36.2 C37.1 L17.2 R128.1 U9.4(V+)
5V: L9.1 L10.1 L14.1
5V_1: C28.1 D12.3 U1.1(AVDD)
5V_2: C35.1 D14.3 U5.1(AVDD)
5V_3: C18.1 D16.3 U8.1(AVDD)
GND: C14.1 C15.2 C20.2 C21.1 C22.2 C23.2 C24.2 C25.2 C29.1 C30.2 C31.2 C32.2 C36.1 C37.2 C40.1 C41.1 C45.1 C131.1 C132.1 GND_1.1 GND_2.1 GND_3.1 R130.2 U1.5(DGND) U3.13(GND) U4.13(GND) U5.5(DGND) U6.13(GND) U8.5(DGND) U9.11(V-)
GND_AMC1: C28.2 D13.3(A) R147.1 U1.4(AGND) ; off-sheet Vinv_A  [also labelled Vinv_A]
GND_AMC2: C35.2 D15.3(A) R150.1 U5.4(AGND) ; off-sheet Vinv_B  [also labelled Vinv_B]
GND_AMC3: C18.2 D17.3(A) R153.1 U8.4(AGND) ; off-sheet Vinv_C  [also labelled Vinv_C]
Igrid_A: R145.1 ; off-sheet Igrid_A
Igrid_B: R148.1 ; off-sheet Igrid_B
Igrid_C: R151.1 ; off-sheet Igrid_C
Iind_A: U3.1(IN) U3.2(IN) U3.3(IN) ; off-sheet Iind_A
Iind_A_Rtn: U3.8(OUT) U3.9(OUT) U3.10(OUT) ; off-sheet Iind_A_Rtn
Iind_B: U4.1(IN) U4.2(IN) U4.3(IN) ; off-sheet Iind_B
Iind_B_Rtn: U4.8(OUT) U4.9(OUT) U4.10(OUT) ; off-sheet Iind_B_Rtn
Iind_C: U6.1(IN) U6.2(IN) U6.3(IN) ; off-sheet Iind_C
Iind_C_Rtn: U6.8(OUT) U6.9(OUT) U6.10(OUT) ; off-sheet Iind_C_Rtn
ILA_Fdbk: C41.2 R28.2 ; off-sheet ILA_Fdbk
ILA_N: C77.2 R19.2 R26.1 U9.2(IN_A-)
ILA_P: R20.2 R30.2 U9.3(IN_A+)
ILB_Fdbk: C40.2 R27.2 ; off-sheet ILB_Fdbk
ILB_N: C79.2 R21.2 R25.1 U9.6(IN_B-)
ILB_P: R22.2 R29.2 U9.5(IN_B+)
ILC_Fdbk: C45.2 R40.2 ; off-sheet ILC_Fdbk
ILC_N: C81.2 R23.2 R31.1 U9.9(IN_C-)
ILC_P: R24.2 R33.2 U9.10(IN_C+)
SD_CLKI: U1.7(CLKIN) U5.7(CLKIN) U8.7(CLKIN) ; off-sheet SD_CLKI
SD_Data_IG_A: R146.2 ; off-sheet SD_Data_IG_A
SD_Data_IG_B: R149.2 ; off-sheet SD_Data_IG_B
SD_Data_IG_C: R152.2 ; off-sheet SD_Data_IG_C
NetC14_2: C14.2 C15.1 L7.2 U8.8(DVDD)
NetC20_1: C20.1 C21.2 L8.2 U1.8(DVDD)
NetC22_1: C22.1 C23.1 L9.2 U3.14(UC)
NetC24_1: C24.1 C25.1 L10.2 U4.14(UC)
NetC29_2: C29.2 C30.1 L13.2 U5.8(DVDD)
NetC31_1: C31.1 C32.1 L14.2 U6.14(UC)
NetC77_1: C77.1 R26.2 R28.1 U9.1(OUT_A)
NetC78_1: C78.1 D12.2 D13.1(C) R145.2 U1.2(AINP)
NetC78_2: C78.2 D12.1 D13.2(C) R147.2 U1.3(AINN)
NetC79_1: C79.1 R25.2 R27.1 U9.7(OUT_B)
NetC80_1: C80.1 D14.2 D15.1(C) R148.2 U5.2(AINP)
NetC80_2: C80.2 D14.1 D15.2(C) R150.2 U5.3(AINN)
NetC81_1: C81.1 R31.2 R40.1 U9.8(OUT_C)
NetC82_1: C82.1 D16.2 D17.1(C) R151.2 U8.2(AINP)
NetC82_2: C82.2 D16.1 D17.2(C) R153.2 U8.3(AINN)
NetC132_2: C132.2 R128.2 R130.1 U9.12(IN_D+)
NetR19_1: R19.1 U3.11(VREF)
NetR20_1: R20.1 U3.12(VOUT)
NetR21_1: R21.1 U4.11(VREF)
NetR22_1: R22.1 U4.12(VOUT)
NetR23_1: R23.1 U6.11(VREF)
NetR24_1: R24.1 U6.12(VOUT)
NetR129_1: R129.1 U9.13(IN_D-) U9.14(OUT_D)
NetR146_1: R146.1 U1.6(DOUT)
NetR149_1: R149.1 U5.6(DOUT)
NetR152_1: R152.1 U8.6(DOUT)

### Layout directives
differential pair: ILA_N, ILA_P, ILB_N, ILB_P, ILC_N, ILC_P

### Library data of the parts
C14 C18 C21 C23 C25 C28 C29 C32 C35 = CMP-0006979-5: as C46 on sheet TIDA-01606-E6_POWERCARD_Controller Card_Pg6
C15 C20 C30 = CMP-0008132-2: CAP, CERM, 2.2 uF, 10 V, +/- 10%, X5R, 0805; Manufacturer: MuRata; TaMin_C: -55°C; Polarized: N; SizeAreaWB_mm2: 6.75; Value1: 0.009 ohm; U/M: EA; Value: 2.2uF; TaMax_C: 85°C; SizeZ_mm: 1.45; SizeX_mm: 2; SizeY_mm: 1.25; Cap_Case: 0805; SizeArea_mm2: 2.5; Cap_F: 2.2µF; AEC Category: Q200; ESR_ohm: 9m
C22 C24 C31 = CMP-0080740-1: CAP, CERM, 10 µF, 25 V,+/- 10%, X7R, 1206; Manufacturer: TDK; Polarized: N; Value: 10uF; U/M: EA; TaMin_C: -55°C; TaMax_C: 125°C; Cap_Case: 1206; AEC Category: Q200; SizeArea_mm2: 5.12; SizeAreaWB_mm2: 10.92; SizeX_mm: 3.2; SizeY_mm: 1.6; SizeZ_mm: 1.8
C36 C40 C41 C45 C131 C132 = CMP-0006979-5: CAP, CERM, 0.1 uF, 25 V, +/- 10%, X7R, 0603; Manufacturer: Kemet; Polarized: N; Value: 0.1uF; U/M: EA; Cap_F: 100nF; Value1: Unknown; TaMin_C: -55°C; TaMax_C: 125°C; SizeArea_mm2: 1.28; SizeAreaWB_mm2: 4.68; SizeX_mm: 1.6; SizeY_mm: 0.8; SizeZ_mm: 1; AEC Category: Q200
C37 = CMP-0006867-4: CAP, CERM, 1 uF, 25 V, +/- 10%, X7R, 0603; Manufacturer: Kemet; Polarized: N; Value: 1uF; U/M: EA; Cap_F: 1µF; Value1: Unknown; TaMin_C: -55°C; TaMax_C: 125°C; SizeArea_mm2: 1.28; SizeAreaWB_mm2: 4.68; SizeX_mm: 1.6; SizeY_mm: 0.8; SizeZ_mm: 1; AEC Category: Q200
C77 C79 C81 = CMP-0083857-1: as C118 on sheet TIDA-01606-E6_POWERCARD_Controller Card_Pg6
C78 C80 C82 = CMP-0006799-4: CAP, CERM, 82 pF, 50 V, +/- 5%, C0G/NP0, 0603; Manufacturer: AVX; Polarized: N; Value: 82pF; U/M: EA; ESR_ohm: 1.31d; Value1: 0.131 ohm; VDC_V: 50V; TaMin_C: -55°C; TaMax_C: 125°C; SizeArea_mm2: 1.28; SizeAreaWB_mm2: 4.68; SizeX_mm: 1.6; SizeY_mm: 0.8; SizeZ_mm: 1; AEC Category: Q200
D12 D14 D16 = CMP-0005922-4: Diode, TVS, Uni, 27 V, SOT-23; Manufacturer: ON Semiconductor; Value1: 40W; RJA_CperW: 556; SizeAreaWB_mm2: 14; SizeArea_mm2: 7.5; SizeX_mm: 2.5; SizeY_mm: 3; SizeZ_mm: 1.1; AEC Category: Q101
D13 D15 D17 = CMP-0005926-4: Diode, TVS, Uni, 33 V, 46 Vc, SOT-23; Manufacturer: ON Semiconductor; Value1: 40W; RJA_CperW: 417; SizeAreaWB_mm2: 14; SizeArea_mm2: 7.5; SizeX_mm: 2.5; SizeY_mm: 3; SizeZ_mm: 1.1; AEC Category: Q101; AEC Qualified: N; Ipp: 870mA; Vbr_Max: 34.65V; Vbr_Min: 31.35V; Vc: 46V
GND_1-GND_3 = CMP-0055137-1: as TP1 on sheet TIDA-01606-E6_POWERCARD_Controller Card_Pg6
L7-L10 L13 L14 L17 = CMP-0003155-2: Ferrite Bead, 26 ohm @ 100 MHz, 6.5 A, 0603; Manufacturer: Wurth Elektronik; Ztyp@1GHz_Ohm: 35.506; ZTyp@100MHz_Ohm: 26; SizeAreaWB_mm2: 4.68; DCR_ohm: 5m; Value1: 0.005 ohm; Value: 26 ohm; Imax_A: 6.5A; SizeZ_mm: 1; SizeX_mm: 1.6; SizeY_mm: 0.8; SizeArea_mm2: 1.28
R19-R24 = CMP-0092407-1: Res Thick Film 0603 100K Ohm 0.1% 0.2W(1/5W) ±50ppm/°C Pad SMD Automotive T/R; Manufacturer: Panasonic; Power_W: 200mW; VDC_V: 150V; AEC Qualified: Yes; SizeZ_mm: 0.55mm; AEC Grade: Grade 0
R25 R26 R29-R31 R33 = CRCW0603100KFKEA: RES, 100 k, 1%, 0.1 W, 0603; Manufacturer: Vishay-Dale; CompType: Resistor; Value: 100k; Res_ohm: 100000; Tolerance_%: 1; Power_W: 0.1; Value2: 0.1W; VDC_V: 75; TempCo: 100 ppm/C; SizeArea_mm2: 1.28; SizeX_mm: 1.6; SizeY_mm: 0.8; EIA_Code: E96; U/M: EA; AEC Category: Q200; Green_Lifecycle: Active; Green_REACh: Passed
R27 R28 R40 = CMP-0022553-4: as R38 on sheet TIDA-01606-E6_POWERCARD_Controller Card_Pg6
R128 R130 = CMP-0023404-3: RES, 10.0 k, 0.1%, 0.1 W, 0603; Manufacturer: Susumu Co Ltd; Value: 10.0k; Res_ohm: 10k; Value_Code: 10k0; Power_W: 100mW; Value2: 0.1W; VDC_V: 75V; TempCo: 25 ppm/C; SizeArea_mm2: 1.28; SizeX_mm: 1.6; SizeY_mm: 0.8; SizeZ_mm: 1; EIA_Code: E192; U/M: EA; AEC Category: Q200
R129 = CMP-0025703-4: RES, 10, 5%, 0.1 W, AEC-Q200 Grade 0, 0603; Manufacturer: Vishay-Dale; Value: 10; Value_Code: 10R0; Power_W: 100mW; Value2: 0.1W; VDC_V: 75V; TempCo: 200 ppm/C; SizeArea_mm2: 1.28; SizeX_mm: 1.6; SizeY_mm: 0.8; SizeZ_mm: 1; EIA_Code: E24; AEC Category: Q200; AEC Qualified: Y; AEC Grade: 0
R145 R147 R148 R150 R151 R153 = CMP-0021995-5: RES, 105, 1%, 0.1 W, AEC-Q200 Grade 0, 0603; Manufacturer: Vishay-Dale; Value: 105; Value_Code: 105R; Power_W: 100mW; Value2: 0.1W; VDC_V: 75V; TempCo: 100 ppm/C; SizeArea_mm2: 1.28; SizeX_mm: 1.6; SizeY_mm: 0.8; SizeZ_mm: 1; EIA_Code: E96; AEC Category: Q200; AEC Qualified: Y; AEC Grade: 0
R146 R149 R152 = CMP-0023039-4: RES, 33.0, 1%, 0.1 W, 0603; Manufacturer: Yageo; Power_W: 100mW; TempCo: 100 ppm/C; Value_Code: 33R0; Value: 33.0; Res_ohm: 33; SizeX_mm: 1.6; SizeY_mm: 0.8; SizeZ_mm: 1; Value2: 0.1W; SizeArea_mm2: 1.28; AEC Qualified: N; VDC_V: 75V; AEC Category: Q200; SizeAreaWB_mm2: 4.68
U1 U5 U8 = CMP-0013494-3: Small Reinforced Isolated Modulator With +/-50mV Input and CMOS Interface, DWV0008A (SOIC-8); Manufacturer: Texas Instruments; SizeArea_mm2: 67.275; CompType: IC; AEC Qualified: N; SizeX_mm: 11.5; SizeZ_mm: 2.8; SizeAreaWB_mm2: 105.975; AEC Category: Q200; Rating: Catalog; SizeY_mm: 5.85
U3 U4 U6 = CMP-0086107-1: Current Sensor 15A 1 Channel Flux Gate, Closed Loop Bidirectional Module, TH; Manufacturer: LEM; SizeAreaWB_mm2: 368.214; SizeZ_mm: 17; SizeY_mm: 21.91; SizeArea_mm2: 293.594; SizeX_mm: 13.4
U9 = CMP-0041120-1: Single-Supply, Rail-to-Rail Operational Amplifier MicroAmplifier(TM) Series, 2.7 to 5 V, -40 to 85 degC, 14-pin SOIC (D14), Green (RoHS & no Sb/Br); Manufacturer: Texas Instruments; Vio (25C)(Max)(mV): 0.5; Iq per channel(Max)(mA): 0.95; Slew Rate(Typ)(V/us): 6; Number of Channels: 4; Total Supply Voltage(Max)(+5V is 5, +/-5V is 10): 5; IIB(Max)(pA): 10; Offset Drift(Typ)(uV/C): 2.5; Vn at 1kHz(Typ)(nV/rtHz): 25; Total Supply Voltage(Min)(+5V is 5, +/-5V is 10): 2.7; Sub Family: Low Input Bias Current Amp (<=10pA), Low Offset Voltage Amplifier (<=500uV), Low Supply Voltage Amplifier (<=2.7V), Precision Amplifier; CMRR(Min)(dB): 80

## Sheet TIDA-01606-E6_POWERCARD_Hardware_Pg7.SchDoc
size 431 x 279 mm; Date: Not shown in title block; ApprovedBy: Not shown in title block; CheckedBy: Not shown in title block; Author: Not shown in title block; CompanyName: Not shown in title block; DrawnBy: Murali P; Engineer: Not shown in title block; Organization: Not shown in title block; Address1: Not shown in title block; Address2: Not shown in title block; Address3: Not shown in title block; Address4: Not shown in title block; DocumentNumber: 1; Revision: Use project parameter SCH_Rev; SheetNumber: 7; SheetTotal: 7; PageSetup: Record=PageOptions¦CenterHorizontal=True¦CenterVertical=True¦PrintScale=1.00¦XCorrection=1.00¦YCorrection=1.00¦PrintKind=0¦BorderSize=5000000¦LeftOffset=0¦BottomOffset=0¦Orientation=2¦PaperLength=1000¦PaperWidth=1000¦Scale=100¦PaperSource=15¦PrintQuality=600¦MediaType=1¦DitherType=10¦PaperKind=Letter¦PrintScaleMode=1
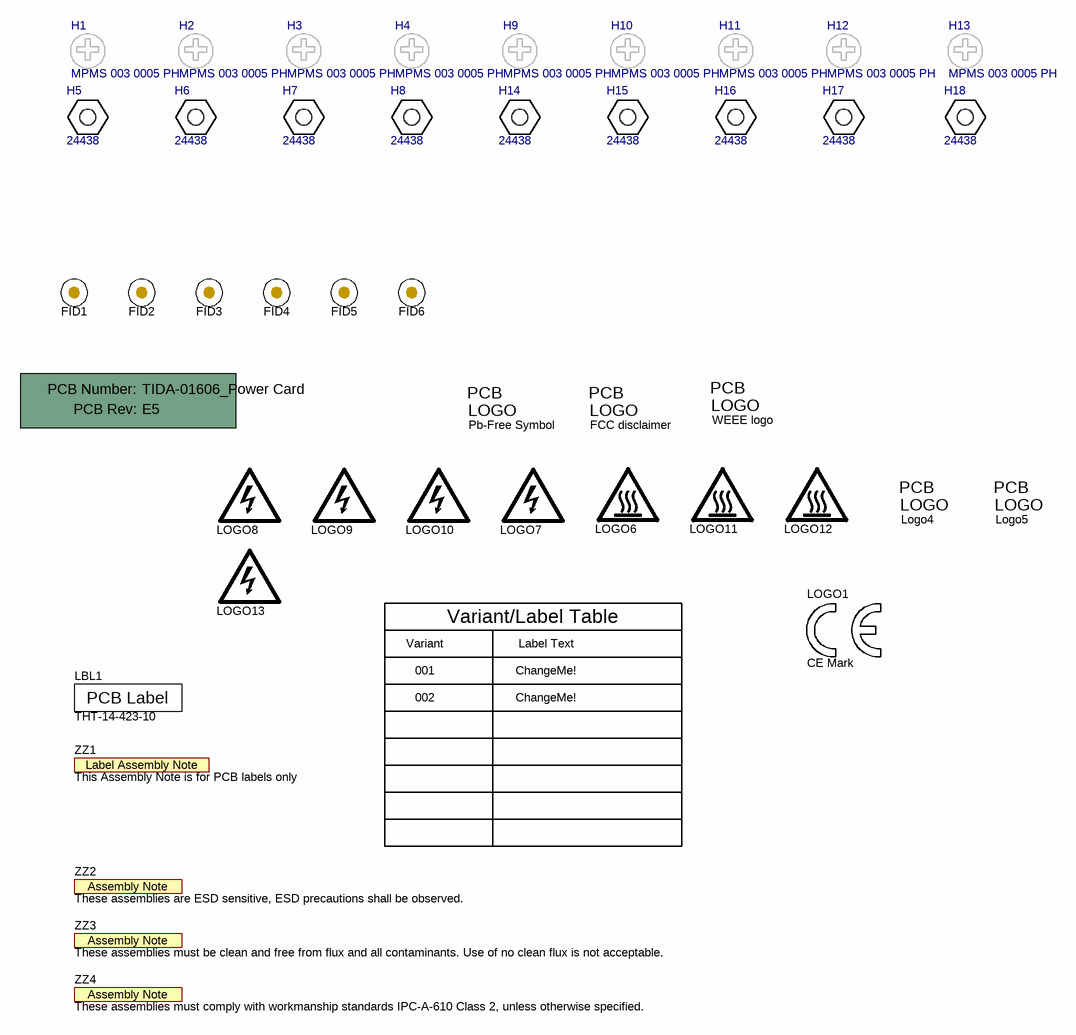
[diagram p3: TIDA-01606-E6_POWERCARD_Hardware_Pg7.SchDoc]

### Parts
!PCB1  Printed Circuit Board  (value not drawn)  (mechanical)
FID1  Fiducial  [Fiducial10-30]  (value not drawn)
FID2  Fiducial  [Fiducial10-30]  (value not drawn)
FID3  Fiducial  [Fiducial10-30]  (value not drawn)
FID4  Fiducial  [Fiducial10-30]  (value not drawn)
FID5  Fiducial  [Fiducial10-30]  (value not drawn)
FID6  Fiducial  [Fiducial10-30]  (value not drawn)
H1  MPMS 003 0005 PH  [BuildingFastener_MPMS_003_0005_PH]
H2  MPMS 003 0005 PH  [BuildingFastener_MPMS_003_0005_PH]
H3  MPMS 003 0005 PH  [BuildingFastener_MPMS_003_0005_PH]
H4  MPMS 003 0005 PH  [BuildingFastener_MPMS_003_0005_PH]
H5  24438  [Keystone24438]
H6  24438  [Keystone24438]
H7  24438  [Keystone24438]
H8  24438  [Keystone24438]
H9  MPMS 003 0005 PH  [BuildingFastener_MPMS_003_0005_PH]
H10  MPMS 003 0005 PH  [BuildingFastener_MPMS_003_0005_PH]
H11  MPMS 003 0005 PH  [BuildingFastener_MPMS_003_0005_PH]
H12  MPMS 003 0005 PH  [BuildingFastener_MPMS_003_0005_PH]
H13  MPMS 003 0005 PH  [BuildingFastener_MPMS_003_0005_PH]
H14  24438  [Keystone24438]
H15  24438  [Keystone24438]
H16  24438  [Keystone24438]
H17  24438  [Keystone24438]
H18  24438  [Keystone24438]
LBL1  THT-14-423-10  [Label_650x200]
LOGO1  CE Mark  [CE_Mark_5mm]  (no BOM)
Logo2  Pb-Free Symbol  [Pb-Free_Overlay_Medium]  (no BOM)
Logo3  FCC disclaimer  [FCC_disclaimer]  (no BOM)
Logo4  CAUTION.  READ USER GUIDE BEFORE USE  [IEC_Caution_Medium]  (value not drawn)  (no BOM)
Logo5  ESD Susceptible  [ESD_Overlay_Medium]  (value not drawn)  (no BOM)
LOGO6  CAUTION HOT SURFACE  [IEC_HotSurface_Medium]  (value not drawn)  (no BOM)
LOGO7  DANGER HIGH VOLTAGE  [IEC_HighVoltage_Medium]  (value not drawn)  (no BOM)
LOGO8  DANGER HIGH VOLTAGE  [IEC_HighVoltage_Medium]  (value not drawn)  (no BOM)
LOGO9  DANGER HIGH VOLTAGE  [IEC_HighVoltage_Medium]  (value not drawn)  (no BOM)
LOGO10  DANGER HIGH VOLTAGE  [IEC_HighVoltage_Medium]  (value not drawn)  (no BOM)
LOGO11  CAUTION HOT SURFACE  [IEC_HotSurface_Medium]  (value not drawn)  (no BOM)
LOGO12  CAUTION HOT SURFACE  [IEC_HotSurface_Medium]  (value not drawn)  (no BOM)
LOGO13  DANGER HIGH VOLTAGE  [IEC_HighVoltage_Medium]  (value not drawn)  (no BOM)
Logo14  WEEE logo  [WEEE_Minimum]  (no BOM)
ZZ1  This Assembly Note is for PCB labels only  [AssemblyNoteLabel]  (no BOM)
ZZ2  These assemblies are ESD sensitive, ESD precautions shall be observed.  [AssemblyNote]  (no BOM)
ZZ3  These assemblies must be clean and free from flux and all contaminants. Use of no clean flux is not acceptable.  [AssemblyNote]  (no BOM)
ZZ4  These assemblies must comply with workmanship standards IPC-A-610 Class 2, unless otherwise specified.  [AssemblyNote]  (no BOM)

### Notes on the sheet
- Variant
- Variant/Label Table
- Label Text
- 001
- 002
- ChangeMe!

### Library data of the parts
!PCB1 = CMP-0003618-2: Manufacturer: Any; PartNumber: TIDA-01606_Power Card
FID1-FID6 = CMP-0077181-1: Fiducial mark.  There is nothing to buy or mount.
H1-H4 H9-H13 = CMP-0003646-1: MACHINE SCREW PAN PHILLIPS M3 5mm; Manufacturer: B&F Fastener Supply; CompType: Hardware
H5-H8 H14-H18 = CMP-0003640-1: Standoff, Hex,25mm Length, M3, Aluminum; Manufacturer: Keystone; CompType: Hardware
LBL1 = CMP-0003625-1: Thermal Transfer Printable Labels, 0.650" W x 0.200" H - 10,000 per roll; Manufacturer: Brady; Note: Size: 0.65" x 0.20 "
LOGO1 = CMP-0074844-1: SymbolCreator: a0412235
Logo2 = CMP-0074839-1: SymbolCreator: a0412235
Logo3 = CMP-0074847-1: FCC_disclaimer
Logo4 = CMP-0074836-1: IEC 61010-1 Caution Warning; SymbolCreator: a0412235; Lib Reference: IEC_Caution; Library Reference: Logo
Logo5 = CMP-0074840-1: ESD Susceptible Symbol; SymbolCreator: a0412235; Lib Reference: ESD_Susceptible; Library Reference: Logo
LOGO6 LOGO11 LOGO12 = CMP-0074837-1: IEC 61010-1 Hot Surface Warning; SymbolCreator: a0412235; Lib Reference: IEC_HotSurface
LOGO7-LOGO10 LOGO13 = CMP-0074835-1: IEC 61010-1 High Voltage Warning; SymbolCreator: a0412235; Lib Reference: IEC_HighVoltage
Logo14 = CMP-0074769-1
ZZ1 = CMP-0003616-3
ZZ2 = CMP-0077236-1
ZZ3 = CMP-0077237-1
ZZ4 = CMP-0077238-1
